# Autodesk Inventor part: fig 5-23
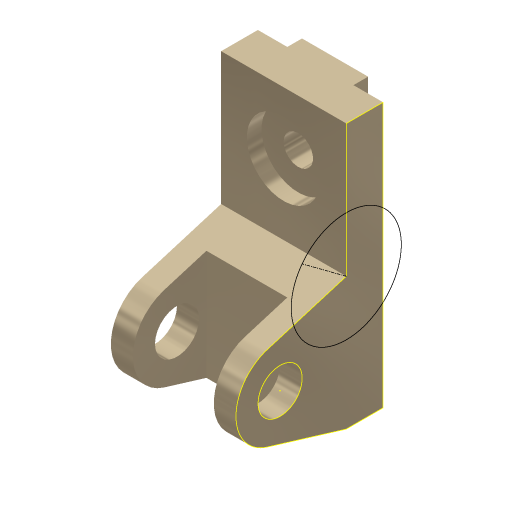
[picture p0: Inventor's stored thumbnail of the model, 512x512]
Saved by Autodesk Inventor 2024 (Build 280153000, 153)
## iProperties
Shininess: 65.0
Angle Display Precision: 2
Document Length Units: 11269
Document Angle Units: 11279
Document Time Units: 11290
Document Mass Units: 11283
Document Length Units Precision: 3
Document Angle Units Precision: 2
Compacted: False
Created: 2001-11
Part Number: fig 5-23
Document SubType Name: Modeling
Designer: Renu Muthoo
Density: 1 g/cm^3
Material: Generic
Appearance: Metal-Titanium (Polished)
Density: 0.0
Volumn: 0.0
Area: 0.0
PropertySet Name: Model Information
Control State: 0
Master: False
Checked Out: False
Author: Renu Muthoo
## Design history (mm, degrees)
sketch "Sketch2"
  geometry: L1 (33.257, 104.664)-(33.257, -75.336); L2 (33.257, -75.336)-(8.257, -75.336); L3 (8.257, -75.336)-(-45.451, -59.045); L4 (-45.451, -1.628)-(8.257, 14.664); L5 (8.257, 14.664)-(8.257, 104.664); L6 (8.257, 104.664)-(33.257, 104.664); C1 r 15 at (-36.743, -30.336); A1 r 30 centre (-36.743, -30.336) between (-45.451, -1.628) and (-45.451, -59.045)
  constraints: 12 end point, 2 centre point, 2 equal length, 2 parallel, 2 point on circle, 2 tangent, 1 coincident, 1 perpendicular, 1 vertical
  dimensions: "d0" = 180 distance of L1.start L1.end; "d1" = 30 radius of A1; "d2" = 25 distance of L5.end L1.start; "d3" = 45 distance from line of L2 A1.centre; "d4" = 70 distance from line of L1 A1.centre; "d5" = 30 diameter of C1
extrude "Extrusion1" new body sketch "Sketch2" distance "d6" = 85; taper "d7" = 0 deg
workplane "Work Plane1"
sketch "Sketch3"
  geometry: L1 (15, 62.364)-(70, 62.364); L2 (70, 62.364)-(70, -52.386); L3 (70, -52.386)-(15, -52.386); L4 (15, -52.386)-(15, 62.364); L5 (0, -45)-(0, -28.708) reference
  constraints: 8 end point, 2 parallel, 1 horizontal, 1 perpendicular
  dimensions: "d8" = 55 distance of L1.start L1.end; "d9" = 15 distance between parallel lines of L5 L4
extrude "Extrusion2" cut sketch "Sketch3" distance "d10" = 50; taper "d11" = 0 deg
sketch "Sketch4"
  geometry: L1 (0, 25)-(85, 25) reference; L2 (0, 0)-(0, 25) reference; L3 (20, 25)-(65, 25); L4 (65, 25)-(65, 35); L5 (65, 35)-(20, 35); L6 (20, 35)-(20, 25)
  constraints: 8 end point, 2 parallel, 1 horizontal, 1 perpendicular, 1 point on line
  dimensions: "d12" = 45 distance of L4.end L5.end; "d13" = 10 distance of L3.end L4.end; "d14" = 20 distance between parallel lines of L2 L6
extrude "Extrusion3" join sketch "Sketch4" stored distance "d15" = 50; taper "d16" = 0 deg
sketch "Sketch5"
  geometry: L1 (85, 0)-(85, 90) reference; L2 (0, 90)-(85, 90) reference; 1 further point
  dimensions: "d17" = 42 distance from line of L2 point (42.5, 48); "d18" = 42.5 distance from line of L1 point (42.5, 48)
hole "Hole1" sketch "Sketch5" diameter "d19" = 20; stored, may be unused: countersink angle "d23" = 82 deg, drill point angle "d25" = 118 deg; dims "d20" = 6, "d21" = 50, "d22" = 10, "d24" = 8
sketch "Sketch8"
  geometry: L1 (75.336, 33.257)-(75.336, 8.257) reference; L2 (-104.664, 33.257)-(75.336, 33.257) reference; L3 (-104.664, 8.257)-(-104.664, 33.257) reference; L4 (-14.664, 8.257)-(-104.664, 8.257) reference; L5 (1.628, -45.451)-(-14.664, 8.257) reference; L6 (75.336, 8.257)-(59.045, -45.451) reference; C1 r 15 at (30.336, -36.743) reference; C2 r 37.437 at (-14.664, 8.257); A1 r 30 centre (30.336, -36.743) between (1.628, -45.451) and (59.045, -45.451) reference
  constraints: 1 centre point, 1 coincident
sketch "Sketch9"
  geometry: L1 (75.336, 33.257)-(75.336, 8.257) reference; L2 (-14.664, 8.257)-(-104.664, 8.257) reference; L3 (1.628, -45.451)-(-14.664, 8.257) reference; L4 (75.336, 8.257)-(59.045, -45.451) reference; L5 (-14.664, 8.257)-(-37, -21.743); C1 r 15 at (30.336, -36.743) reference; A1 r 30 centre (30.336, -36.743) between (1.628, -45.451) and (59.045, -45.451) reference
  constraints: 2 end point
body "Solid1"
node "Sketch1"
